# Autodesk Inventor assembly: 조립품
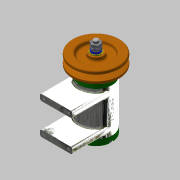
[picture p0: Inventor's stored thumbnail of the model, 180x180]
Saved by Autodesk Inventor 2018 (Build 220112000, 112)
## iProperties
Created: 2020-07
Part Number: 조립품
Material: 일반
Document SubType Name: Assembly
Designer: home
Author: home
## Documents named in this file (15)
- C:\Users\home\Desktop\700706V1026\조립품.iam
- C:\Users\home\Desktop\700706V1026\본체.ipt
- C:\Users\home\Desktop\700706V1026\베어링 6002.ipt
- C:\Users\home\Desktop\700706V1026\앞커버.ipt
- C:\Users\home\Desktop\700706V1026\오일 실 15 25 7.ipt
- C:\Users\home\Desktop\700706V1026\축.ipt
- C:\Users\home\Desktop\700706V1026\키 3x3x12.ipt
- C:\Users\home\Desktop\700706V1026\V벨트풀리.ipt
- C:\Users\home\Desktop\700706V1026\와셔 8x17.ipt
- C:\Users\home\Desktop\700706V1026\스프링와셔 8.ipt
- C:\Users\home\Desktop\700706V1026\너트 M8.ipt
- C:\Users\home\Desktop\700706V1026\볼트 M4x12.ipt
- C:\Users\home\Desktop\700706V1026\뒤커버.ipt
- C:\Users\home\Desktop\700706V1026\와셔 6x11.5.ipt
- C:\Users\home\Desktop\700706V1026\볼트 M6x8.ipt
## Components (1 placed, 1 different names)
1. V벨트풀리:1
